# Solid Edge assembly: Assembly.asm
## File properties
Author: Deepak Maini
Template: Normal.asm
Last saved by: CADCIM
Revision: 16
Application: Solid Edge
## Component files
Casting.par
Brasses.par
Cap.par
Bolt.par
Nut.par
Lock Nut.par
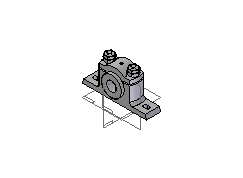
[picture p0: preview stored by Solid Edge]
